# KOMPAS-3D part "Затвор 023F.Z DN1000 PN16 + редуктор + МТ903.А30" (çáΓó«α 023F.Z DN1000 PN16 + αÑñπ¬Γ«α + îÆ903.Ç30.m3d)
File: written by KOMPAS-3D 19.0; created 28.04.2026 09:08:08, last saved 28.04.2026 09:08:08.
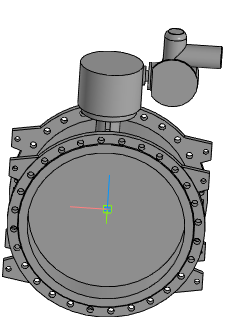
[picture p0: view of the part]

Document properties: Полное имя файла: ..\..\Затвор 023F.Z DN400-DN1600 + редуктор + МТ903\Затвор 023F.Z DN1000 PN16 + редуктор + МТ903.А30.a3d

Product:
- Part/product: Затвор 023F.Z DN1000 PN16 + редуктор + МТ903.А30
    Масса: 1759.45

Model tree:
1. Операция без истории:1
